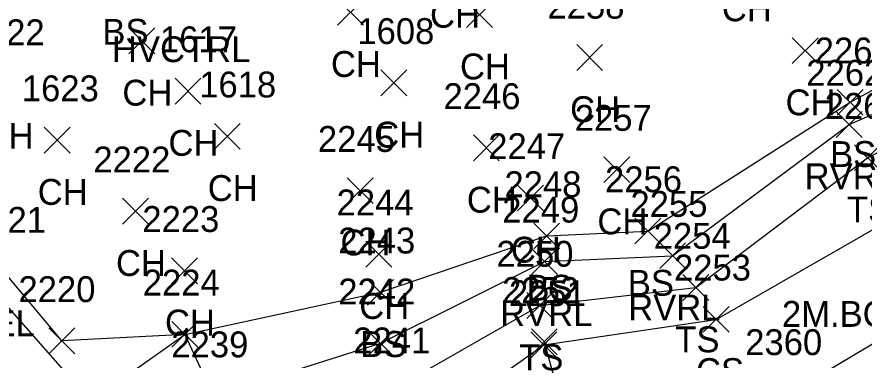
# Model space of a CAD drawing. Extents: x 1504228 to 1506103, y 437717 to 440106.
# Drawn here: x 1505265.5 to 1505331, y 438187.4 to 438213.9 of the extents above; entities that cross this region are included whole.
import ezdxf

# ---------------------------------------------------------------- set-up
doc = ezdxf.new("R2010")
doc.units = 0
for name, color, linetype in [('C_A', 7, 'Continuous'), ('D_I', 7, 'Continuous'), ('D_TIC', 7, 'Continuous'), ('DCP', 7, 'Continuous'), ('L_A', 7, 'Continuous'), ('L_C', 7, 'Continuous'), ('L_I', 7, 'Continuous'), ('L_TIC', 7, 'Continuous'), ('LABL', 7, 'Continuous'), ('LARO', 7, 'Continuous'), ('LAWE', 7, 'Continuous'), ('LELB', 7, 'Continuous'), ('UW', 7, 'Continuous')]:
    doc.layers.add(name, color=color, linetype=linetype)

msp = doc.modelspace()

# ---------------------------------------------------------------- linework, layer by layer
at = {"layer": 'D_TIC'}
for points in [[(1505305.265, 438187.781), (1505307.265, 438189.781)], [(1505307.265, 438187.781), (1505305.265, 438189.781)]]:
    msp.add_lwpolyline(points, dxfattribs=at)
at = {"layer": 'DCP'}
msp.add_lwpolyline([(1505306.265, 438188.781), (1505322.088, 438131.045)], dxfattribs=at)
at = {"layer": 'L_TIC'}
for points in [[(1505290.292, 438213.251), (1505292.292, 438215.251)], [(1505292.292, 438213.251), (1505290.292, 438215.251)], [(1505300.263, 438213.06), (1505302.263, 438215.06)], [(1505302.263, 438213.06), (1505300.263, 438215.06)], [(1505274.173, 438211.035), (1505276.173, 438213.035)], [(1505276.173, 438211.035), (1505274.173, 438213.035)], [(1505325.418, 438210.285), (1505327.418, 438212.285)], [(1505327.418, 438210.285), (1505325.418, 438212.285)], [(1505308.768, 438209.757), (1505310.768, 438211.757)], [(1505310.768, 438209.757), (1505308.768, 438211.757)], [(1505293.636, 438207.792), (1505295.636, 438209.792)], [(1505295.636, 438207.792), (1505293.636, 438209.792)], [(1505277.738, 438207.156), (1505279.738, 438209.156)], [(1505279.738, 438207.156), (1505277.738, 438209.156)], [(1505328.9, 438206.293), (1505330.9, 438208.293)], [(1505330.9, 438206.293), (1505328.9, 438208.293)], [(1505328.815, 438204.572), (1505330.815, 438206.572)], [(1505330.815, 438204.572), (1505328.815, 438206.572)], [(1505267.634, 438203.368), (1505269.634, 438205.368)], [(1505269.634, 438203.368), (1505267.634, 438205.368)], [(1505280.774, 438203.665), (1505282.774, 438205.665)], [(1505282.774, 438203.665), (1505280.774, 438205.665)], [(1505300.79, 438202.765), (1505302.79, 438204.765)], [(1505302.79, 438202.765), (1505300.79, 438204.765)], [(1505330.239, 438202.009), (1505332.239, 438204.009)], [(1505332.239, 438202.009), (1505330.239, 438204.009)], [(1505310.877, 438201.087), (1505312.877, 438203.087)], [(1505312.877, 438201.087), (1505310.877, 438203.087)], [(1505291.031, 438199.459), (1505293.031, 438201.459)], [(1505293.031, 438199.459), (1505291.031, 438201.459)], [(1505304.192, 438198.899), (1505306.192, 438200.899)], [(1505306.192, 438198.899), (1505304.192, 438200.899)], [(1505273.681, 438197.872), (1505275.681, 438199.872)], [(1505275.681, 438197.872), (1505273.681, 438199.872)], [(1505313.273, 438196.344), (1505315.273, 438198.344)], [(1505315.273, 438196.344), (1505313.273, 438198.344)], [(1505305.445, 438195.96), (1505307.445, 438197.96)], [(1505307.445, 438195.96), (1505305.445, 438197.96)], [(1505292.478, 438194.552), (1505294.478, 438196.552)], [(1505294.478, 438194.552), (1505292.478, 438196.552)], [(1505315.183, 438194.439), (1505317.183, 438196.439)], [(1505317.183, 438194.439), (1505315.183, 438196.439)], [(1505305.287, 438193.997), (1505307.287, 438195.997)], [(1505307.287, 438193.997), (1505305.287, 438195.997)], [(1505277.468, 438193.27), (1505279.468, 438195.27)], [(1505279.468, 438193.27), (1505277.468, 438195.27)], [(1505292.602, 438191.608), (1505294.602, 438193.608)], [(1505294.602, 438191.608), (1505292.602, 438193.608)], [(1505316.977, 438191.973), (1505318.977, 438193.973)], [(1505318.977, 438191.973), (1505316.977, 438193.973)], [(1505304.914, 438190.586), (1505306.914, 438192.586)], [(1505306.914, 438190.586), (1505304.914, 438192.586)], [(1505318.546, 438189.519), (1505320.546, 438191.519)], [(1505320.546, 438189.519), (1505318.546, 438191.519)], [(1505277.498, 438188.358), (1505279.498, 438190.358)], [(1505279.498, 438188.358), (1505277.498, 438190.358)], [(1505277.498, 438188.358), (1505279.498, 438190.358)], [(1505279.498, 438188.358), (1505277.498, 438190.358)], [(1505267.982, 438187.852), (1505269.982, 438189.852)], [(1505269.982, 438187.852), (1505267.982, 438189.852)], [(1505292.606, 438187.67), (1505294.606, 438189.67)], [(1505294.606, 438187.67), (1505292.606, 438189.67)], [(1505305.221, 438187.545), (1505307.221, 438189.545)], [(1505307.221, 438187.545), (1505305.221, 438189.545)], [(1505305.221, 438187.545), (1505307.221, 438189.545)], [(1505307.221, 438187.545), (1505305.221, 438189.545)]]:
    msp.add_lwpolyline(points, dxfattribs=at)
at = {"layer": 'LABL'}
msp.add_lwpolyline([(1505412.94, 438279.434), (1505408.751, 438263.902), (1505393.358, 438239.3), (1505379.992, 438219.583), (1505364.652, 438204.996), (1505342.27, 438194.948), (1505325.182, 438184.758), (1505314.631, 438179.74), (1505312.566, 438178.307), (1505308.953, 438177.263), (1505304.583, 438176.7), (1505296.615, 438175.22), (1505299.292, 438169.398), (1505303.904, 438164.856), (1505308.252, 438160.874), (1505313.047, 438161.473), (1505317.495, 438164.603), (1505327.49, 438169.4), (1505342.058, 438174.403)], dxfattribs=at)
at = {"layer": 'LARO'}
for points in [[(1505268.982, 438188.852), (1505264.509, 438194.206), (1505257.789, 438202.997)], [(1505278.498, 438189.358), (1505268.982, 438188.852)], [(1505278.498, 438189.358), (1505280.716, 438184.584)]]:
    msp.add_lwpolyline(points, dxfattribs=at)
at = {"layer": 'LAWE'}
msp.add_lwpolyline([(1505191.715, 438146.002), (1505202.906, 438148.803), (1505214.791, 438151.569), (1505218.42, 438155.881), (1505225.066, 438161.326), (1505233.297, 438167.151), (1505239.085, 438170.522), (1505246.461, 438173.024), (1505251.729, 438176.792), (1505260.319, 438178.7), (1505267.708, 438179.756), (1505273.159, 438181.503), (1505280.716, 438184.584), (1505293.606, 438188.67), (1505306.287, 438194.997), (1505316.183, 438195.439), (1505329.815, 438205.572), (1505347.823, 438213.433)], dxfattribs=at)
at = {"layer": 'LELB'}
for points in [[(1505258.116, 438181.066), (1505268.339, 438182.172), (1505278.498, 438189.358), (1505293.602, 438192.608), (1505306.445, 438196.96), (1505314.273, 438197.344), (1505329.9, 438207.293), (1505346.396, 438216.217), (1505367.728, 438232.021), (1505378.412, 438248.378), (1505391.234, 438272.553), (1505398.951, 438287.599)], [(1505287.419, 438180.921), (1505294.194, 438184.889), (1505305.914, 438191.586), (1505317.977, 438192.973), (1505331.239, 438203.009), (1505347.587, 438211.637), (1505370.579, 438230.634), (1505379.879, 438246.354), (1505394.187, 438272.178), (1505403.001, 438285.772)], [(1505306.221, 438188.545), (1505319.546, 438190.519), (1505334.224, 438198.941), (1505350.38, 438205.602), (1505370.579, 438230.634)], [(1505215.631, 438142.954), (1505216.782, 438152.684), (1505223.21, 438155.651), (1505231.417, 438162.88), (1505240.87, 438166.496), (1505250.977, 438169.557), (1505260.591, 438172.084), (1505271.035, 438170.915), (1505277.265, 438170.598), (1505281.518, 438175.58), (1505287.828, 438178.641), (1505292.056, 438179.708), (1505296.753, 438181.832), (1505306.221, 438188.545)]]:
    msp.add_lwpolyline(points, dxfattribs=at)
at = {"layer": 'UW'}
msp.add_lwpolyline([(1505283.181, 438170.638), (1505251.335, 438206.763), (1505225.076, 438243.18)], dxfattribs=at)

# ---------------------------------------------------------------- texts
at = {"layer": 'C_A'}
msp.add_text('HVCTRL', height=2, dxfattribs=at).set_placement((1505272.859, 438210.393))
at = {"layer": 'D_I'}
msp.add_text('2252', height=2, dxfattribs=at).set_placement((1505303.005, 438191.781))
at = {"layer": 'L_A'}
for s, p in [('CH', (1505319.98, 438213.554)), ('CH', (1505297.435, 438213.058)), ('BS', (1505272.118, 438211.738)), ('CH', (1505289.781, 438209.251)), ('CH', (1505299.751, 438209.06)), ('CH', (1505273.662, 438207.035)), ('CH', (1505324.906, 438206.285)), ('CH', (1505308.257, 438205.757)), ('CH', (1505262.939, 438203.701)), ('CH', (1505293.124, 438203.792)), ('CH', (1505277.226, 438203.156)), ('BS', (1505328.341, 438202.293)), ('RVRL', (1505326.382, 438200.572)), ('CH', (1505280.262, 438199.665)), ('CH', (1505267.122, 438199.368)), ('CH', (1505300.278, 438198.765)), ('TS', (1505329.649, 438198.009)), ('CH', (1505310.365, 438197.087)), ('CH', (1505290.52, 438195.459)), ('CH', (1505303.68, 438194.899)), ('CH', (1505273.169, 438193.872)), ('BS', (1505312.714, 438192.344)), ('BS', (1505304.886, 438191.96)), ('CH', (1505291.966, 438190.552)), ('RVRL', (1505312.749, 438190.439)), ('RVRL', (1505302.854, 438189.997)), ('LEL', (1505262.147, 438189.206)), ('CH', (1505276.956, 438189.27)), ('BS', (1505292.043, 438187.608)), ('TS', (1505316.386, 438187.973)), ('TS', (1505304.324, 438186.586)), ('CS', (1505317.987, 438185.519))]:
    msp.add_text(s, height=2, dxfattribs=at).set_placement(p)
at = {"layer": 'L_C'}
msp.add_text('2M.BOXELDER', height=2, dxfattribs=at).set_placement((1505324.626, 438189.941))
at = {"layer": 'L_I'}
for s, p in [('2258', (1505306.508, 438213.757)), ('1622', (1505261.711, 438211.701)), ('1608', (1505291.817, 438211.792)), ('1617', (1505276.565, 438211.156)), ('2261', (1505327.16, 438210.293)), ('2262', (1505326.508, 438208.572)), ('1623', (1505265.894, 438207.368)), ('1618', (1505279.601, 438207.665)), ('2246', (1505298.475, 438206.765)), ('2263', (1505327.932, 438206.009)), ('2257', (1505308.617, 438205.087)), ('2245', (1505288.771, 438203.459)), ('2247', (1505301.932, 438202.899)), ('2222', (1505271.421, 438201.872)), ('2256', (1505310.958, 438200.344)), ('2248', (1505303.185, 438199.96)), ('2244', (1505290.218, 438198.552)), ('2255', (1505312.923, 438198.439)), ('2249', (1505303.019, 438197.997)), ('2221', (1505261.816, 438197.206)), ('2223', (1505275.208, 438197.27)), ('2243', (1505290.342, 438195.608)), ('2254', (1505314.717, 438195.973)), ('2250', (1505302.568, 438194.586)), ('2253', (1505316.286, 438193.519)), ('2224', (1505275.238, 438192.358)), ('2224', (1505275.238, 438192.358)), ('2220', (1505265.635, 438191.852)), ('2242', (1505290.346, 438191.67)), ('2251', (1505303.529, 438191.545)), ('2251', (1505303.529, 438191.545)), ('2241', (1505291.502, 438187.889)), ('2360', (1505321.789, 438187.758)), ('2239', (1505277.449, 438187.584)), ('2239', (1505277.449, 438187.584))]:
    msp.add_text(s, height=2, dxfattribs=at).set_placement(p)

doc.saveas('drawing.dxf')
